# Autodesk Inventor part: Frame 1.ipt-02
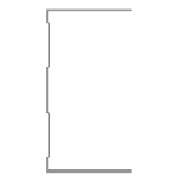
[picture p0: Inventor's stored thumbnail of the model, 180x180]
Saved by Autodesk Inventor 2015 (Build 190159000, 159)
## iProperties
IsCustomPart: 1
Created: 2015-04
Part Number: Frame 1.ipt-02
Material: Aluminum 6061
Description: Kévin Novo
Document SubType Name: Modeling
Standard: Kevin
Designer: suporte
Standards Organization: Kevin
Language: en-US
Size Designation: (Unnamed 2)
Categories: <MemberInstance><Categories><Category DisplayName="Structural Shapes" InternalName="089c4875-fa83-4c05-b084-43b9cc11f5ed" Mnemonic="GRDR"><CategoryParameter Dis
Density: 2.7 g/cm^3
Appearance: Aluminum - Flat
_CCFamilyMember: 2
_CCFamilyDisplayName: Kévin - Kévin Novo
_FrameMemberDoc: Frame Member File
_Version: 15.0.0
_GetPNFromCC: 1
G_W: 50,000 mm
G_H: 75,000 mm
G_L: 600,000 mm
Author: suporte
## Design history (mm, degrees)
node "Start Plane"
node "End Plane"
sketch "Sketch"
  geometry: L1 (24.7, 37.5)-(24.7, 36.9); L2 (24.7, 36.9)-(-24.7, 36.9); L3 (-24.7, -36.9)-(24.7, -36.9); L4 (24.7, -36.9)-(24.7, -37.5); L5 (24.7, -37.5)-(-25.3, -37.5); L6 (-25.3, 37.5)-(24.7, 37.5); L7 (-24.7, 36.9)-(-24.7, 31.9); L8 (-24.7, 31.9)-(-23.3, 30.5); L9 (-23.3, 30.5)-(-23.3, 10.934); L10 (-23.3, 10.934)-(-24.7, 9.534); L11 (-24.7, 9.534)-(-24.7, -9.534); L12 (-24.7, -9.534)-(-23.3, -10.934); L13 (-23.3, -10.934)-(-23.3, -30.5); L14 (-23.3, -30.5)-(-24.7, -31.9); L15 (-24.7, -31.9)-(-24.7, -36.9); L16 (-25.3, -37.5)-(-25.3, -31.651); L17 (-25.3, -31.651)-(-23.9, -30.251); L18 (-23.9, -30.251)-(-23.9, -11.183); L19 (-23.9, -11.183)-(-25.3, -9.783); L20 (-25.3, -9.783)-(-25.3, 9.783); L21 (-25.3, 9.783)-(-23.9, 11.183); L22 (-23.9, 11.183)-(-23.9, 30.251); L23 (-23.9, 30.251)-(-25.3, 31.651); L24 (-25.3, 31.651)-(-25.3, 37.5); L25 (-25.3, 0)-(30.37, 0); 3 further points
  constraints: 50 end point, 10 point on line, 9 parallel, 5 perpendicular, 4 equal length, 3 midpoint, 3 vertical, 2 vertical alignment, 1 collinear, 1 horizontal, 1 horizontal alignment
  dimensions: "d3" = 0.6 distance of L1.start L1.end (= d6); "d5" = 75 distance between parallel lines of L5 L6; "d6" = 0.6 distance between parallel lines of L24 L7 (= d8); "d7" = 0.6 distance between parallel lines of L8 L23 (= d8); "d8" = 0.6 distance between parallel lines of L22 L9 (= d12); "Espessura" = 0.6 distance between parallel lines of L17 L14; "d10" = 0.6 distance between parallel lines of L13 L18 (= Espessura); "d11" = 0.6 distance between parallel lines of L12 L19 (= Espessura); "d12" = 0.6 distance between parallel lines of L21 L10 (= d11); "d13" = 5 distance of L2.end L7.end; "d15" = 135 deg angle of L9 L8; "d16" = 2 distance between parallel lines of L24 L9; "d17" = 50 distance of L6.start L1.start
extrude "Body" join sketch "Sketch" stored distance "d24" = 0.13; taper "d25" = 0 deg
node "Driven Length"
  sketch "Sketch10"
    geometry: L1 (0, 0)-(10, 0) reference
    constraints: 2 end point, 1 horizontal
  workplane "Work Plane7"
  sketch "Sketch11"
    geometry: L1 (-2, 0)-(12, 0) reference; L2 (-2, 600)-(12, 600) reference
    dimensions: "d27" = 600 distance between parallel lines of L1 L2 (derived)
body "Solid1"
other parameters: "G_OFFSET_START" = 0 [user parameter; used in 1 equation term], "G_OFFSET_END" = 0 [user parameter; used in 1 equation term], "d22" = 0 (computed from G_OFFSET_START), "G_L" = 600 (= d27) [user parameter], "d34" = 90 deg
